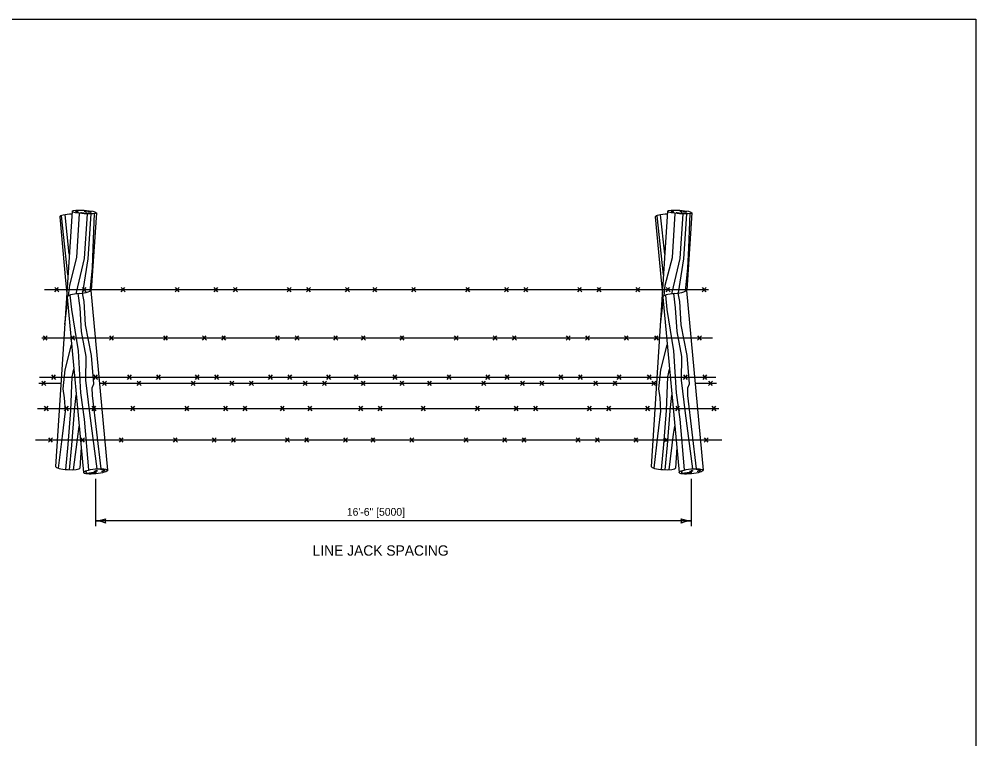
# Model space of a CAD drawing. Extents: x 49991.4 to 50021, y 49987.6 to 50011.4.
# Drawn here: x 50009.35 to 50016.75, y 49993.43 to 49999 of the extents above; entities that cross this region are included whole.
import ezdxf

# ---------------------------------------------------------------- set-up
doc = ezdxf.new("R2010")
doc.units = 0
for name, color, linetype in [('Level 1', 7, 'Continuous'), ('Level 2', 7, 'Continuous'), ('Level 3', 7, 'Continuous')]:
    doc.layers.add(name, color=color, linetype=linetype)

msp = doc.modelspace()

# ---------------------------------------------------------------- linework, layer by layer
at = {"layer": 'Level 1'}
for p, q in [((50009.7558, 49997.5117), (50009.6287, 49995.5359)), ((50009.6599, 49997.4696), (50009.7058, 49996.9764)), ((50009.9436, 49997.5002), (50009.9046, 49996.9012)), ((50014.3649, 49997.5117), (50014.2377, 49995.5359)), ((50014.2689, 49997.4696), (50014.3148, 49996.9764)), ((50014.5526, 49997.5002), (50014.5136, 49996.9012)), ((50009.7058, 49996.9764), (50009.7149, 49996.8774)), ((50014.3148, 49996.9764), (50014.324, 49996.8774)), ((50009.542, 49996.9051), (50014.6799, 49996.9051)), ((50009.6221, 49996.887), (50009.6514, 49996.9217)), ((50009.6528, 49996.887), (50009.6234, 49996.9217)), ((50009.8354, 49996.887), (50009.8648, 49996.9217)), ((50009.8661, 49996.887), (50009.8368, 49996.9217)), ((50009.9017, 49996.8978), (50010.0312, 49995.5072)), ((50010.1354, 49996.887), (50010.1648, 49996.9217)), ((50010.1661, 49996.887), (50010.1368, 49996.9217)), ((50010.5542, 49996.887), (50010.5836, 49996.9217)), ((50010.5849, 49996.887), (50010.5556, 49996.9217)), ((50010.8542, 49996.887), (50010.8836, 49996.9217)), ((50010.8849, 49996.887), (50010.8556, 49996.9217)), ((50011.0042, 49996.887), (50011.0336, 49996.9217)), ((50011.0349, 49996.887), (50011.0056, 49996.9217)), ((50011.4209, 49996.887), (50011.4502, 49996.9217)), ((50011.4516, 49996.887), (50011.4222, 49996.9217)), ((50011.5709, 49996.887), (50011.6002, 49996.9217)), ((50011.6016, 49996.887), (50011.5722, 49996.9217)), ((50011.8709, 49996.887), (50011.9002, 49996.9217)), ((50011.9016, 49996.887), (50011.8722, 49996.9217)), ((50012.0842, 49996.887), (50012.1136, 49996.9217)), ((50012.1149, 49996.887), (50012.0856, 49996.9217)), ((50012.3842, 49996.887), (50012.4136, 49996.9217)), ((50012.4149, 49996.887), (50012.3856, 49996.9217)), ((50012.803, 49996.887), (50012.8324, 49996.9217)), ((50012.8337, 49996.887), (50012.8044, 49996.9217)), ((50013.103, 49996.887), (50013.1324, 49996.9217)), ((50013.1337, 49996.887), (50013.1044, 49996.9217)), ((50013.253, 49996.887), (50013.2824, 49996.9217)), ((50013.2837, 49996.887), (50013.2544, 49996.9217)), ((50013.6697, 49996.887), (50013.699, 49996.9217)), ((50013.7004, 49996.887), (50013.671, 49996.9217)), ((50013.8197, 49996.887), (50013.849, 49996.9217)), ((50013.8504, 49996.887), (50013.821, 49996.9217)), ((50014.1197, 49996.887), (50014.149, 49996.9217)), ((50014.1504, 49996.887), (50014.121, 49996.9217)), ((50014.3526, 49996.887), (50014.382, 49996.9217)), ((50014.3833, 49996.887), (50014.354, 49996.9217)), ((50014.5108, 49996.8978), (50014.6403, 49995.5072)), ((50014.633, 49996.887), (50014.6624, 49996.9217)), ((50014.6637, 49996.887), (50014.6344, 49996.9217)), ((50009.7178, 49996.8476), (50009.8443, 49995.4893)), ((50014.3268, 49996.8476), (50014.4534, 49995.4893)), ((50009.5224, 49996.5319), (50014.7109, 49996.5319)), ((50009.5327, 49996.5137), (50009.562, 49996.5484)), ((50009.5634, 49996.5137), (50009.534, 49996.5484)), ((50009.746, 49996.5137), (50009.7754, 49996.5484)), ((50009.7767, 49996.5137), (50009.7474, 49996.5484)), ((50010.046, 49996.5137), (50010.0754, 49996.5484)), ((50010.0767, 49996.5137), (50010.0474, 49996.5484)), ((50010.4648, 49996.5137), (50010.4942, 49996.5484)), ((50010.4955, 49996.5137), (50010.4662, 49996.5484)), ((50010.7648, 49996.5137), (50010.7942, 49996.5484)), ((50010.7955, 49996.5137), (50010.7662, 49996.5484)), ((50010.9148, 49996.5137), (50010.9442, 49996.5484)), ((50010.9455, 49996.5137), (50010.9162, 49996.5484)), ((50011.3315, 49996.5137), (50011.3608, 49996.5484)), ((50011.3622, 49996.5137), (50011.3328, 49996.5484)), ((50011.4815, 49996.5137), (50011.5108, 49996.5484)), ((50011.5122, 49996.5137), (50011.4828, 49996.5484)), ((50011.7815, 49996.5137), (50011.8108, 49996.5484)), ((50011.8122, 49996.5137), (50011.7828, 49996.5484)), ((50011.9948, 49996.5137), (50012.0242, 49996.5484)), ((50012.0255, 49996.5137), (50011.9962, 49996.5484)), ((50012.2948, 49996.5137), (50012.3242, 49996.5484)), ((50012.3255, 49996.5137), (50012.2962, 49996.5484)), ((50012.7136, 49996.5137), (50012.743, 49996.5484)), ((50012.7443, 49996.5137), (50012.715, 49996.5484)), ((50013.0136, 49996.5137), (50013.043, 49996.5484)), ((50013.0443, 49996.5137), (50013.015, 49996.5484)), ((50013.1636, 49996.5137), (50013.193, 49996.5484)), ((50013.1943, 49996.5137), (50013.165, 49996.5484)), ((50013.5803, 49996.5137), (50013.6096, 49996.5484)), ((50013.611, 49996.5137), (50013.5816, 49996.5484)), ((50013.7303, 49996.5137), (50013.7596, 49996.5484)), ((50013.761, 49996.5137), (50013.7316, 49996.5484)), ((50014.0303, 49996.5137), (50014.0596, 49996.5484)), ((50014.061, 49996.5137), (50014.0316, 49996.5484)), ((50014.2632, 49996.5137), (50014.2926, 49996.5484)), ((50014.2939, 49996.5137), (50014.2646, 49996.5484)), ((50014.5963, 49996.5137), (50014.6257, 49996.5484)), ((50014.627, 49996.5137), (50014.5977, 49996.5484)), ((50009.5028, 49996.2285), (50014.7378, 49996.2285)), ((50009.5211, 49996.1618), (50009.5504, 49996.1965)), ((50009.5518, 49996.1618), (50009.5224, 49996.1965)), ((50009.5987, 49996.2104), (50009.6281, 49996.2451)), ((50009.6294, 49996.2104), (50009.6001, 49996.2451)), ((50009.9232, 49996.2104), (50009.9526, 49996.2451)), ((50009.9539, 49996.2104), (50009.9246, 49996.2451)), ((50009.9925, 49996.1618), (50010.0219, 49996.1965)), ((50010.0232, 49996.1618), (50009.9939, 49996.1965)), ((50010.1857, 49996.2104), (50010.2151, 49996.2451)), ((50010.2164, 49996.2104), (50010.1871, 49996.2451)), ((50010.2591, 49996.1618), (50010.2885, 49996.1965)), ((50010.2898, 49996.1618), (50010.2605, 49996.1965)), ((50010.4098, 49996.2104), (50010.4392, 49996.2451)), ((50010.4405, 49996.2104), (50010.4112, 49996.2451)), ((50010.6779, 49996.1618), (50010.7073, 49996.1965)), ((50010.7086, 49996.1618), (50010.6793, 49996.1965)), ((50010.7098, 49996.2104), (50010.7392, 49996.2451)), ((50010.7405, 49996.2104), (50010.7112, 49996.2451)), ((50010.8598, 49996.2104), (50010.8892, 49996.2451)), ((50010.8905, 49996.2104), (50010.8612, 49996.2451)), ((50010.9779, 49996.1618), (50011.0073, 49996.1965)), ((50011.0086, 49996.1618), (50010.9793, 49996.1965)), ((50011.1279, 49996.1618), (50011.1573, 49996.1965)), ((50011.1586, 49996.1618), (50011.1293, 49996.1965)), ((50011.2765, 49996.2104), (50011.3058, 49996.2451)), ((50011.3072, 49996.2104), (50011.2778, 49996.2451)), ((50011.4265, 49996.2104), (50011.4558, 49996.2451)), ((50011.4572, 49996.2104), (50011.4278, 49996.2451)), ((50011.5446, 49996.1618), (50011.5739, 49996.1965)), ((50011.5753, 49996.1618), (50011.5459, 49996.1965)), ((50011.6946, 49996.1618), (50011.7239, 49996.1965)), ((50011.7253, 49996.1618), (50011.6959, 49996.1965)), ((50011.7265, 49996.2104), (50011.7558, 49996.2451)), ((50011.7572, 49996.2104), (50011.7278, 49996.2451)), ((50011.9398, 49996.2104), (50011.9692, 49996.2451)), ((50011.9705, 49996.2104), (50011.9412, 49996.2451)), ((50011.9946, 49996.1618), (50012.0239, 49996.1965)), ((50012.0253, 49996.1618), (50011.9959, 49996.1965)), ((50012.2398, 49996.2104), (50012.2692, 49996.2451)), ((50012.2705, 49996.2104), (50012.2412, 49996.2451)), ((50012.2946, 49996.1618), (50012.3239, 49996.1965)), ((50012.3253, 49996.1618), (50012.2959, 49996.1965)), ((50012.5079, 49996.1618), (50012.5373, 49996.1965)), ((50012.5386, 49996.1618), (50012.5093, 49996.1965)), ((50012.6586, 49996.2104), (50012.688, 49996.2451)), ((50012.6893, 49996.2104), (50012.66, 49996.2451)), ((50012.9267, 49996.1618), (50012.9561, 49996.1965)), ((50012.9574, 49996.1618), (50012.9281, 49996.1965)), ((50012.9586, 49996.2104), (50012.988, 49996.2451)), ((50012.9893, 49996.2104), (50012.96, 49996.2451)), ((50013.1086, 49996.2104), (50013.138, 49996.2451)), ((50013.1393, 49996.2104), (50013.11, 49996.2451)), ((50013.2267, 49996.1618), (50013.2561, 49996.1965)), ((50013.2574, 49996.1618), (50013.2281, 49996.1965)), ((50013.3767, 49996.1618), (50013.4061, 49996.1965)), ((50013.4074, 49996.1618), (50013.3781, 49996.1965)), ((50013.5253, 49996.2104), (50013.5546, 49996.2451)), ((50013.556, 49996.2104), (50013.5266, 49996.2451)), ((50013.6753, 49996.2104), (50013.7046, 49996.2451)), ((50013.706, 49996.2104), (50013.6766, 49996.2451)), ((50013.7934, 49996.1618), (50013.8227, 49996.1965)), ((50013.8241, 49996.1618), (50013.7947, 49996.1965)), ((50013.9434, 49996.1618), (50013.9727, 49996.1965)), ((50013.9741, 49996.1618), (50013.9447, 49996.1965)), ((50013.9753, 49996.2104), (50014.0046, 49996.2451)), ((50014.006, 49996.2104), (50013.9766, 49996.2451)), ((50014.2082, 49996.2104), (50014.2376, 49996.2451)), ((50014.2389, 49996.2104), (50014.2096, 49996.2451)), ((50014.2434, 49996.1618), (50014.2727, 49996.1965)), ((50014.2741, 49996.1618), (50014.2447, 49996.1965)), ((50014.4886, 49996.2104), (50014.518, 49996.2451)), ((50014.5193, 49996.2104), (50014.49, 49996.2451)), ((50014.6386, 49996.2104), (50014.668, 49996.2451)), ((50014.6693, 49996.2104), (50014.64, 49996.2451)), ((50014.6813, 49996.1618), (50014.7107, 49996.1965)), ((50014.712, 49996.1618), (50014.6827, 49996.1965)), ((50009.4997, 49996.18), (50009.6701, 49996.18)), ((50009.9686, 49996.18), (50014.2792, 49996.18)), ((50014.5776, 49996.18), (50014.7436, 49996.18)), ((50009.4872, 49995.9858), (50014.7617, 49995.9858)), ((50009.5416, 49995.9676), (50009.5709, 49996.0023)), ((50009.5723, 49995.9676), (50009.5429, 49996.0023)), ((50009.6977, 49995.9676), (50009.727, 49996.0023)), ((50009.7284, 49995.9676), (50009.699, 49996.0023)), ((50009.911, 49995.9676), (50009.9404, 49996.0023)), ((50009.9417, 49995.9676), (50009.9124, 49996.0023)), ((50009.9655, 49995.9988), (50009.9655, 49995.9988)), ((50010.211, 49995.9676), (50010.2404, 49996.0023)), ((50010.2417, 49995.9676), (50010.2124, 49996.0023)), ((50010.6298, 49995.9676), (50010.6592, 49996.0023)), ((50010.6605, 49995.9676), (50010.6312, 49996.0023)), ((50010.9298, 49995.9676), (50010.9592, 49996.0023)), ((50010.9605, 49995.9676), (50010.9312, 49996.0023)), ((50011.0798, 49995.9676), (50011.1092, 49996.0023)), ((50011.1105, 49995.9676), (50011.0812, 49996.0023)), ((50011.3691, 49995.9676), (50011.3984, 49996.0023)), ((50011.3998, 49995.9676), (50011.3704, 49996.0023)), ((50011.5824, 49995.9676), (50011.6118, 49996.0023)), ((50011.6131, 49995.9676), (50011.5838, 49996.0023)), ((50011.9756, 49995.9676), (50012.0049, 49996.0023)), ((50012.0063, 49995.9676), (50011.9769, 49996.0023)), ((50012.1256, 49995.9676), (50012.1549, 49996.0023)), ((50012.1563, 49995.9676), (50012.1269, 49996.0023)), ((50012.4598, 49995.9676), (50012.4892, 49996.0023)), ((50012.4905, 49995.9676), (50012.4612, 49996.0023)), ((50012.8786, 49995.9676), (50012.908, 49996.0023)), ((50012.9093, 49995.9676), (50012.88, 49996.0023)), ((50013.1786, 49995.9676), (50013.208, 49996.0023)), ((50013.2093, 49995.9676), (50013.18, 49996.0023)), ((50013.3286, 49995.9676), (50013.358, 49996.0023)), ((50013.3593, 49995.9676), (50013.33, 49996.0023)), ((50013.7453, 49995.9676), (50013.7746, 49996.0023)), ((50013.776, 49995.9676), (50013.7466, 49996.0023)), ((50013.8953, 49995.9676), (50013.9246, 49996.0023)), ((50013.926, 49995.9676), (50013.8966, 49996.0023)), ((50014.1953, 49995.9676), (50014.2246, 49996.0023)), ((50014.226, 49995.9676), (50014.1966, 49996.0023)), ((50014.4282, 49995.9676), (50014.4576, 49996.0023)), ((50014.4589, 49995.9676), (50014.4296, 49996.0023)), ((50014.5746, 49995.9988), (50014.5746, 49995.9988)), ((50014.7086, 49995.9676), (50014.738, 49996.0023)), ((50014.7393, 49995.9676), (50014.71, 49996.0023)), ((50009.5743, 49995.7232), (50009.6036, 49995.7579)), ((50009.605, 49995.7232), (50009.5756, 49995.7579)), ((50009.8216, 49995.7232), (50009.851, 49995.7579)), ((50009.8523, 49995.7232), (50009.823, 49995.7579)), ((50010.1216, 49995.7232), (50010.151, 49995.7579)), ((50010.1523, 49995.7232), (50010.123, 49995.7579)), ((50010.5404, 49995.7232), (50010.5698, 49995.7579)), ((50010.5711, 49995.7232), (50010.5418, 49995.7579)), ((50010.8404, 49995.7232), (50010.8698, 49995.7579)), ((50010.8711, 49995.7232), (50010.8418, 49995.7579)), ((50010.9904, 49995.7232), (50011.0198, 49995.7579)), ((50011.0211, 49995.7232), (50010.9918, 49995.7579)), ((50011.4071, 49995.7232), (50011.4364, 49995.7579)), ((50011.4378, 49995.7232), (50011.4084, 49995.7579)), ((50011.5571, 49995.7232), (50011.5864, 49995.7579)), ((50011.5878, 49995.7232), (50011.5584, 49995.7579)), ((50011.8571, 49995.7232), (50011.8864, 49995.7579)), ((50011.8878, 49995.7232), (50011.8584, 49995.7579)), ((50012.0704, 49995.7232), (50012.0998, 49995.7579)), ((50012.1011, 49995.7232), (50012.0718, 49995.7579)), ((50012.3704, 49995.7232), (50012.3998, 49995.7579)), ((50012.4011, 49995.7232), (50012.3718, 49995.7579)), ((50012.7892, 49995.7232), (50012.8186, 49995.7579)), ((50012.8199, 49995.7232), (50012.7906, 49995.7579)), ((50013.0892, 49995.7232), (50013.1186, 49995.7579)), ((50013.1199, 49995.7232), (50013.0906, 49995.7579)), ((50013.2392, 49995.7232), (50013.2686, 49995.7579)), ((50013.2699, 49995.7232), (50013.2406, 49995.7579)), ((50013.6559, 49995.7232), (50013.6852, 49995.7579)), ((50013.6866, 49995.7232), (50013.6572, 49995.7579)), ((50013.8059, 49995.7232), (50013.8352, 49995.7579)), ((50013.8366, 49995.7232), (50013.8072, 49995.7579)), ((50014.1059, 49995.7232), (50014.1352, 49995.7579)), ((50014.1366, 49995.7232), (50014.1072, 49995.7579)), ((50014.3388, 49995.7232), (50014.3682, 49995.7579)), ((50014.3695, 49995.7232), (50014.3402, 49995.7579)), ((50014.6479, 49995.7232), (50014.6773, 49995.7579)), ((50014.6786, 49995.7232), (50014.6493, 49995.7579)), ((50009.4715, 49995.7414), (50014.7845, 49995.7414)), ((50009.8263, 49995.6823), (50009.8163, 49995.5237)), ((50014.4354, 49995.6823), (50014.4253, 49995.5237))]:
    msp.add_line(p, q, dxfattribs=at)
msp.add_lwpolyline([(49999.3835, 49998.9992), (50016.7501, 49998.9992), (50016.7501, 49987.7988), (49999.3835, 49987.7988)], close=True, dxfattribs=at)
for points in [[(50009.7242, 49997.0195), (50009.6743, 49997.4772)], [(50009.7344, 49997.1792), (50009.7015, 49997.4835)], [(50009.7293, 49996.8583), (50009.7375, 49996.9385), (50009.7923, 49997.1536), (50009.8143, 49997.4957)], [(50009.7904, 49996.8733), (50009.7908, 49996.8834), (50009.8525, 49997.1474), (50009.8747, 49997.4915)], [(50009.8403, 49996.8793), (50009.8809, 49997.1446), (50009.9034, 49997.4917)], [(50009.895, 49996.8938), (50009.913, 49997.0703), (50009.9198, 49997.2287), (50009.9299, 49997.4942)], [(50014.3332, 49997.0195), (50014.2833, 49997.4772)], [(50014.3435, 49997.1792), (50014.3105, 49997.4835)], [(50014.3383, 49996.8583), (50014.3465, 49996.9385), (50014.4014, 49997.1536), (50014.4233, 49997.4957)], [(50014.3994, 49996.8733), (50014.3998, 49996.8834), (50014.4615, 49997.1474), (50014.4837, 49997.4915)], [(50014.4494, 49996.8793), (50014.49, 49997.1446), (50014.5125, 49997.4917)], [(50014.504, 49996.8938), (50014.522, 49997.0703), (50014.5289, 49997.2287), (50014.539, 49997.4942)], [(50009.8863, 49995.5094), (50009.853, 49995.9017), (50009.8235, 49996.1051), (50009.8047, 49996.4316), (50009.7533, 49996.7512), (50009.7412, 49996.8628)], [(50009.9505, 49995.5183), (50009.8938, 49995.9502), (50009.8632, 49996.2043), (50009.8653, 49996.3872), (50009.8285, 49996.5799), (50009.8176, 49996.765), (50009.8033, 49996.8748)], [(50009.9799, 49995.5191), (50009.913, 49996.0844), (50009.9125, 49996.1453), (50009.9245, 49996.1771), (50009.9071, 49996.395), (50009.8594, 49996.634), (50009.8493, 49996.8124), (50009.8373, 49996.8789)], [(50014.4954, 49995.5094), (50014.4621, 49995.9017), (50014.4325, 49996.1051), (50014.4137, 49996.4316), (50014.3623, 49996.7512), (50014.3502, 49996.8628)], [(50014.5596, 49995.5183), (50014.5028, 49995.9502), (50014.4722, 49996.2043), (50014.4743, 49996.3872), (50014.4375, 49996.5799), (50014.4266, 49996.765), (50014.4123, 49996.8748)], [(50014.589, 49995.5191), (50014.5221, 49996.0844), (50014.5216, 49996.1453), (50014.5335, 49996.1771), (50014.5161, 49996.395), (50014.4685, 49996.634), (50014.4583, 49996.8124), (50014.4464, 49996.8789)], [(50009.6995, 49996.6365), (50009.7212, 49996.8113)], [(50014.3086, 49996.6365), (50014.3302, 49996.8113)], [(50009.6518, 49995.5223), (50009.681, 49995.7707), (50009.7037, 49995.9647), (50009.6982, 49996.0683), (50009.6879, 49996.1381), (50009.703, 49996.2856), (50009.7522, 49996.4784)], [(50014.2609, 49995.5223), (50014.29, 49995.7707), (50014.3128, 49995.9647), (50014.3073, 49996.0683), (50014.297, 49996.1381), (50014.312, 49996.2856), (50014.3612, 49996.4784)], [(50009.7079, 49995.5128), (50009.7255, 49995.7053), (50009.7464, 49995.9705), (50009.7563, 49996.2305), (50009.7699, 49996.2886)], [(50014.3169, 49995.5128), (50014.3345, 49995.7053), (50014.3555, 49995.9705), (50014.3653, 49996.2305), (50014.3789, 49996.2886)], [(50009.7365, 49995.511), (50009.7539, 49995.7023), (50009.7748, 49995.9676), (50009.7886, 49996.0873)], [(50014.3455, 49995.511), (50014.363, 49995.7023), (50014.3839, 49995.9676), (50014.3977, 49996.0873)], [(50009.7673, 49995.5111), (50009.802, 49995.7855), (50009.8108, 49995.8488)], [(50014.3764, 49995.5111), (50014.4111, 49995.7855), (50014.4199, 49995.8488)]]:
    msp.add_lwpolyline(points, dxfattribs=at)
for centre, major_axis, ratio, start_param, end_param in [((50009.7535, 49997.4769), (0.0936, 0.0072), 0.143064, 1.548914, 3.140392), ((50014.3625, 49997.4769), (0.0936, 0.0072), 0.143064, 1.548914, 3.140392), ((50009.8113, 49996.8567), (0.0934, 0.0089), 0.201542, 1.555621, 3.157543), ((50009.8122, 49996.8949), (0.0932, 0.0089), 0.201992, 4.679863, 6.355951), ((50014.4203, 49996.8567), (0.0934, 0.0089), 0.201542, 1.555621, 3.157543), ((50014.4212, 49996.8949), (0.0932, 0.0089), 0.201992, 4.679863, 6.355951), ((50009.7224, 49995.5299), (-0.0937, 0.0061), 0.194104, 0.000064, 3.132664), ((50014.3314, 49995.5299), (-0.0937, 0.0061), 0.194104, 0.000064, 3.132664)]:
    msp.add_ellipse(centre, major_axis=major_axis, ratio=ratio, start_param=start_param, end_param=end_param, dxfattribs=at)
for centre, major_axis, ratio in [((50009.8497, 49997.506), (0.0937, -0.0058), 0.143064), ((50014.4587, 49997.506), (0.0937, -0.0058), 0.143064), ((50009.9376, 49995.4983), (0.0932, 0.0089), 0.201992), ((50014.5466, 49995.4983), (0.0932, 0.0089), 0.201992)]:
    msp.add_ellipse(centre, major_axis=major_axis, ratio=ratio, dxfattribs=at)
for points in [[(50009.8043, 49997.5036), (50009.7988, 49997.5048), (50009.793, 49997.5061), (50009.7887, 49997.5087), (50009.7856, 49997.5114), (50009.7862, 49997.5146), (50009.7901, 49997.5155), (50009.7945, 49997.5164), (50009.8005, 49997.5161)], [(50009.8212, 49997.502), (50009.8265, 49997.502), (50009.8294, 49997.501), (50009.8353, 49997.5002), (50009.8401, 49997.4991), (50009.8459, 49997.4981), (50009.8525, 49997.4971), (50009.856, 49997.4971), (50009.8656, 49997.4977), (50009.8657, 49997.4977), (50009.8718, 49997.4981), (50009.8791, 49997.4977), (50009.8898, 49997.4977), (50009.8957, 49997.4967), (50009.901, 49997.4971), (50009.9058, 49997.4984)], [(50009.8613, 49997.5027), (50009.8668, 49997.5045), (50009.8683, 49997.5048), (50009.8657, 49997.5076), (50009.8647, 49997.5082), (50009.8594, 49997.5098), (50009.8542, 49997.5104), (50009.8499, 49997.5104), (50009.8493, 49997.5108)], [(50009.8756, 49997.5122), (50009.878, 49997.5114), (50009.8814, 49997.5111), (50009.8857, 49997.5104), (50009.8898, 49997.5103), (50009.895, 49997.509), (50009.8972, 49997.5087), (50009.8996, 49997.5073), (50009.9004, 49997.5059), (50009.901, 49997.5048), (50009.901, 49997.5045)], [(50014.4133, 49997.5036), (50014.4078, 49997.5048), (50014.4021, 49997.5061), (50014.3977, 49997.5087), (50014.3947, 49997.5114), (50014.3952, 49997.5146), (50014.3992, 49997.5155), (50014.4036, 49997.5164), (50014.4095, 49997.5161)], [(50014.4303, 49997.502), (50014.4356, 49997.502), (50014.4384, 49997.501), (50014.4444, 49997.5002), (50014.4492, 49997.4991), (50014.4549, 49997.4981), (50014.4615, 49997.4971), (50014.4651, 49997.4971), (50014.4746, 49997.4977), (50014.4747, 49997.4977), (50014.4808, 49997.4981), (50014.4881, 49997.4977), (50014.4988, 49997.4977), (50014.5048, 49997.4967), (50014.51, 49997.4971), (50014.5148, 49997.4984)], [(50014.4704, 49997.5027), (50014.4759, 49997.5045), (50014.4773, 49997.5048), (50014.4747, 49997.5076), (50014.4737, 49997.5082), (50014.4684, 49997.5098), (50014.4633, 49997.5104), (50014.4589, 49997.5104), (50014.4584, 49997.5108)], [(50014.4847, 49997.5122), (50014.4871, 49997.5114), (50014.4905, 49997.5111), (50014.4948, 49997.5104), (50014.4988, 49997.5103), (50014.504, 49997.509), (50014.5063, 49997.5087), (50014.5087, 49997.5073), (50014.5095, 49997.5059), (50014.51, 49997.5048), (50014.51, 49997.5045)], [(50009.868, 49995.4969), (50009.8657, 49995.4959), (50009.8631, 49995.4938), (50009.8623, 49995.4916), (50009.8636, 49995.4894), (50009.8649, 49995.4874), (50009.8673, 49995.4864), (50009.8706, 49995.4855), (50009.8764, 49995.4853), (50009.8846, 49995.4853), (50009.8895, 49995.4861), (50009.895, 49995.4866), (50009.9044, 49995.4881), (50009.9127, 49995.4887), (50009.9194, 49995.4892), (50009.9267, 49995.4898), (50009.9357, 49995.4913), (50009.9439, 49995.4926)], [(50009.9369, 49995.5046), (50009.94, 49995.505), (50009.9442, 49995.5046), (50009.9464, 49995.5043), (50009.9492, 49995.5028), (50009.9494, 49995.5011), (50009.9467, 49995.4993), (50009.9424, 49995.4982), (50009.9376, 49995.4975), (50009.934, 49995.4971), (50009.9285, 49995.4969), (50009.9258, 49995.4969), (50009.9249, 49995.4969)], [(50009.9763, 49995.5152), (50009.9809, 49995.5152), (50009.9854, 49995.5152), (50009.9886, 49995.5145), (50009.9916, 49995.5137), (50009.9963, 49995.5131), (50009.9987, 49995.5122), (50010.0024, 49995.511), (50010.0038, 49995.5102), (50010.005, 49995.509), (50010.0065, 49995.5076), (50010.0074, 49995.5053), (50010.0068, 49995.5043), (50010.0042, 49995.5028), (50009.9987, 49995.5011), (50009.9968, 49995.5005), (50009.9901, 49995.4985), (50009.9877, 49995.498), (50009.9846, 49995.4969), (50009.9832, 49995.4969)], [(50014.477, 49995.4969), (50014.4748, 49995.4959), (50014.4721, 49995.4938), (50014.4714, 49995.4916), (50014.4726, 49995.4894), (50014.4739, 49995.4874), (50014.4763, 49995.4864), (50014.4796, 49995.4855), (50014.4854, 49995.4853), (50014.4937, 49995.4853), (50014.4985, 49995.4861), (50014.504, 49995.4866), (50014.5134, 49995.4881), (50014.5218, 49995.4887), (50014.5284, 49995.4892), (50014.5358, 49995.4898), (50014.5448, 49995.4913), (50014.5529, 49995.4926)], [(50014.5459, 49995.5046), (50014.5491, 49995.505), (50014.5533, 49995.5046), (50014.5554, 49995.5043), (50014.5582, 49995.5028), (50014.5584, 49995.5011), (50014.5558, 49995.4993), (50014.5514, 49995.4982), (50014.5466, 49995.4975), (50014.5431, 49995.4971), (50014.5376, 49995.4969), (50014.5349, 49995.4969), (50014.5339, 49995.4969)], [(50014.5853, 49995.5152), (50014.59, 49995.5152), (50014.5944, 49995.5152), (50014.5977, 49995.5145), (50014.6006, 49995.5137), (50014.6054, 49995.5131), (50014.6077, 49995.5122), (50014.6114, 49995.511), (50014.6128, 49995.5102), (50014.6141, 49995.509), (50014.6156, 49995.5076), (50014.6165, 49995.5053), (50014.6158, 49995.5043), (50014.6133, 49995.5028), (50014.6077, 49995.5011), (50014.6059, 49995.5005), (50014.5991, 49995.4985), (50014.5967, 49995.498), (50014.5937, 49995.4969), (50014.5922, 49995.4969)]]:
    msp.add_spline(points, degree=3, dxfattribs=at)
at = {"layer": 'Level 3'}
for p, q in [((50009.9376, 49995.4393), (50009.9376, 49995.0749)), ((50014.5466, 49995.4393), (50014.5466, 49995.0749)), ((50014.5466, 49995.1149), (50009.9376, 49995.1149))]:
    msp.add_line(p, q, dxfattribs=at)
for centre, radius, start, end in [((50009.9261, 49995.3476), 0.233, 272.82731, 292.07716), ((50009.9284, 49994.8928), 0.2223, 67.45601, 87.63952), ((50010.0658, 49995.1149), 0.0548, 162.13882, 197.86118), ((50014.5558, 49995.3371), 0.2223, 247.45601, 267.63952), ((50014.4184, 49995.1149), 0.0548, 342.13882, 17.86118), ((50014.5581, 49994.8822), 0.233, 92.82731, 112.07716)]:
    msp.add_arc(centre, radius, start, end, dxfattribs=at)

# ---------------------------------------------------------------- texts
at = {"layer": 'Level 2'}
msp.add_text('16\'-6" [5000]', height=0.06, rotation=0, dxfattribs=at).set_placement((50011.8823, 49995.1549))
msp.add_text('LINE JACK SPACING', height=0.08, dxfattribs=at).set_placement((50011.6172, 49994.8457))

doc.saveas('drawing.dxf')
